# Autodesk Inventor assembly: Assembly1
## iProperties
Created: 2005-03
Part Number: Assembly1
Document SubType Name: Weldment
Designer: CADCIM
Manufacturer: Standard
Standards Organization: Custom
Author: CADCIM
